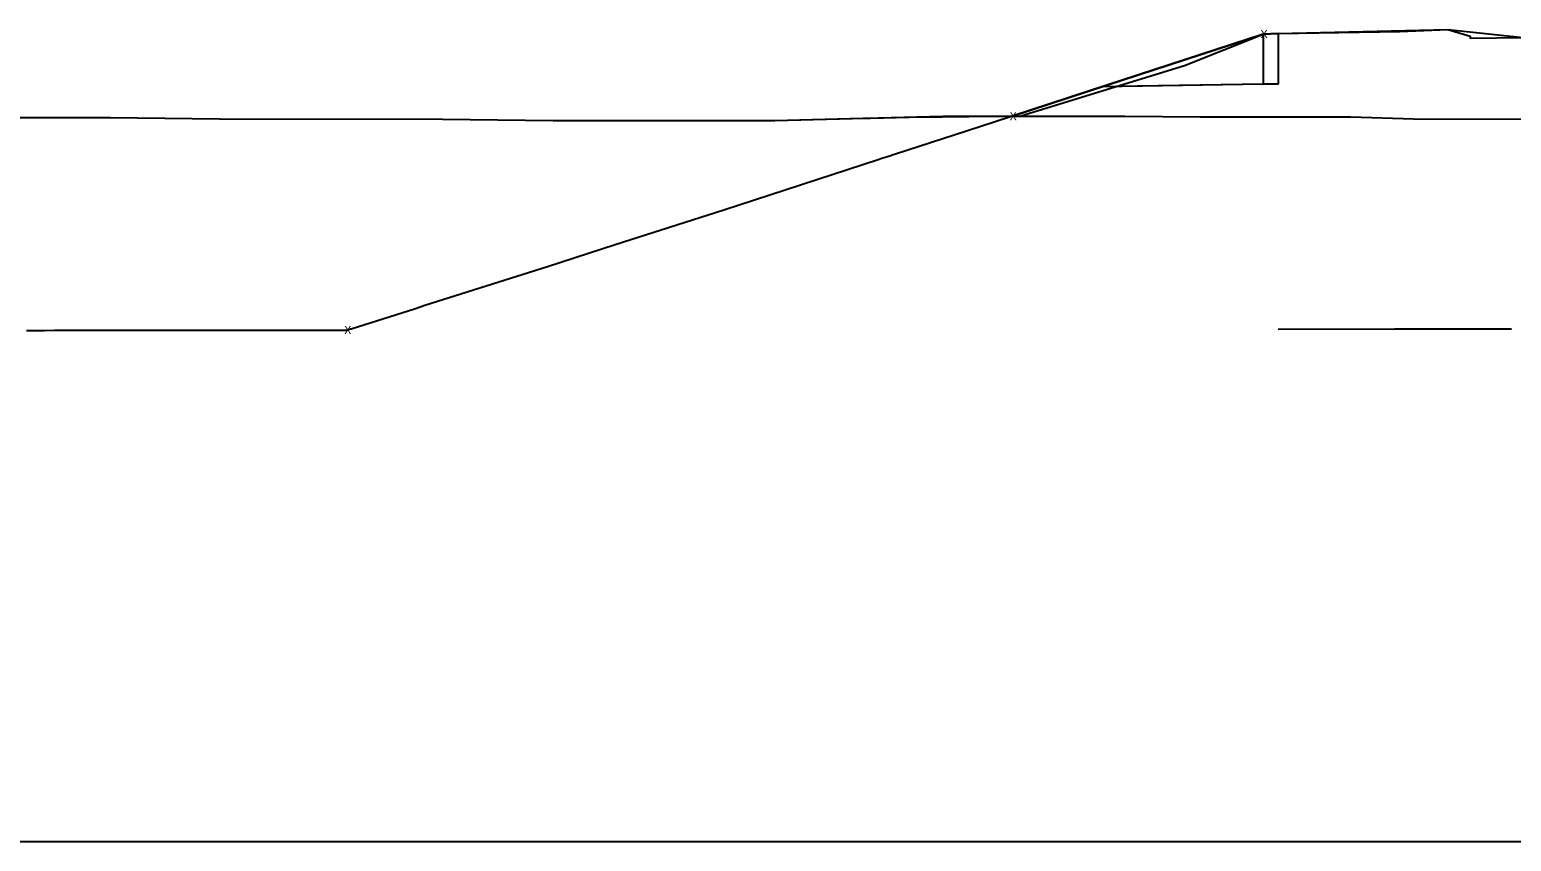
# Model space of a CAD drawing. Extents: x -26 to 303, y -16 to 6048.
# Drawn here: x 85.28 to 129.73, y 4500 to 4524.35 of the extents above; entities that cross this region are included whole.
import ezdxf

# ---------------------------------------------------------------- set-up
doc = ezdxf.new("R2010")
doc.units = 0
for name, color, linetype in [('CONST_DCH', 7, 'Continuous'), ('CONST_LV3', 7, 'Continuous'), ('DTM_P_FINISHED_GRADE2', 7, 'Continuous'), ('DTM_TEMP_DROP', 7, 'Continuous'), ('DTM_X_GROUND', 7, 'Continuous'), ('X_PROFILES_1', 7, 'Continuous'), ('XS_CELL', 7, 'Continuous'), ('XS_M_SHAPES_EARTHWORK', 7, 'Continuous'), ('XS_P_GROUND', 7, 'Continuous'), ('XS_P_SHOULDER', 7, 'Continuous'), ('XS_P_SUBGRADE_GRANULAR', 7, 'Continuous'), ('XS_P_SUBGRADE_GRANULAR_B', 7, 'Continuous')]:
    doc.layers.add(name, color=color, linetype=linetype)

msp = doc.modelspace()

# ---------------------------------------------------------------- linework, layer by layer
at = {"layer": 'CONST_LV3'}
for points in [[(94.797, 4515.34), (94.908, 4515.375), (94.923, 4515.379), (96.854, 4515.99), (97.139, 4516.081), (100.815, 4517.247), (102.845, 4517.902), (106.108, 4518.949), (110.735, 4520.455), (110.846, 4520.491), (111.118, 4520.58), (111.155, 4520.592), (111.252, 4520.623), (113.386, 4521.311), (122.281, 4524.218), (122.395, 4524.222), (122.734, 4524.235)], [(122.734, 4524.235), (122.282, 4524.218), (117.591, 4522.68), (114.756, 4521.754)], [(122.281, 4524.218), (122.734, 4524.235)]]:
    msp.add_lwpolyline(points, dxfattribs=at)
at = {"layer": 'DTM_P_FINISHED_GRADE2'}
msp.add_lwpolyline([(114.756, 4521.754), (114.983, 4521.754), (119.921, 4523.272), (122.282, 4524.218), (122.734, 4524.235), (126.381, 4524.293), (127.822, 4524.351), (128.49, 4524.156), (128.492, 4524.09), (130.083, 4524.118)], dxfattribs=at)
at = {"layer": 'DTM_X_GROUND'}
for points in [[(80.968, 4521.716), (87.694, 4521.711), (90.976, 4521.673), (97.666, 4521.666), (100.982, 4521.628), (107.639, 4521.62), (110.27, 4521.691), (110.506, 4521.697), (111.662, 4521.728), (112.674, 4521.738), (114.259, 4521.754), (114.756, 4521.754), (114.927, 4521.754), (114.983, 4521.754), (119.921, 4523.272), (122.282, 4524.218), (122.394, 4524.222), (122.734, 4524.235), (127.822, 4524.351), (130.083, 4524.118)], [(39.4, 4521.777), (41.51, 4521.773), (49.291, 4521.763), (51.672, 4521.759), (59.183, 4521.749), (61.569, 4521.803), (68.443, 4521.799), (71.992, 4521.729), (78.481, 4521.721), (80.968, 4521.716), (87.694, 4521.711), (90.976, 4521.673), (97.666, 4521.666), (100.982, 4521.628), (107.639, 4521.62), (112.674, 4521.755), (118.136, 4521.753), (120.403, 4521.738), (124.916, 4521.736), (126.788, 4521.673), (132.667, 4521.665)]]:
    msp.add_lwpolyline(points, dxfattribs=at)
at = {"layer": 'XS_CELL'}
msp.add_line((0, 4500), (150, 4500), dxfattribs=at)
at = {"layer": 'XS_M_SHAPES_EARTHWORK'}
for points in [[(117.869, 4522.641), (119.921, 4523.272), (122.282, 4524.218), (122.394, 4524.222), (122.734, 4524.235), (122.734, 4522.721), (122.283, 4522.714)], [(114.756, 4521.754), (114.927, 4521.754), (114.983, 4521.754), (117.869, 4522.641), (117.45, 4522.634)]]:
    msp.add_lwpolyline(points, close=True, dxfattribs=at)
at = {"layer": 'XS_P_GROUND'}
for points in [[(94.797, 4515.34), (94.908, 4515.375), (94.923, 4515.379), (96.854, 4515.99), (97.139, 4516.081), (100.815, 4517.247), (102.845, 4517.902), (106.108, 4518.949), (110.735, 4520.455), (110.846, 4520.491), (111.118, 4520.58), (111.155, 4520.592), (111.252, 4520.623), (113.386, 4521.311), (122.281, 4524.218)], [(114.756, 4521.754), (117.591, 4522.68), (122.282, 4524.218)], [(85.19, 4515.33), (85.725, 4515.33), (86.031, 4515.331), (86.425, 4515.331), (90.789, 4515.336), (90.879, 4515.336), (90.949, 4515.336), (91.036, 4515.336), (91.04, 4515.336), (91.476, 4515.336), (91.478, 4515.336), (91.646, 4515.337), (91.739, 4515.337), (91.933, 4515.337), (93.442, 4515.339), (93.505, 4515.339), (94.772, 4515.34)], [(94.772, 4515.34), (94.797, 4515.34)], [(122.734, 4515.37), (126.225, 4515.374), (126.821, 4515.375), (127.743, 4515.376), (128.783, 4515.377), (129.625, 4515.379), (129.728, 4515.379)]]:
    msp.add_lwpolyline(points, dxfattribs=at)
at = {"layer": 'XS_P_SHOULDER'}
msp.add_lwpolyline([(122.282, 4524.218), (122.734, 4524.235)], dxfattribs=at)
at = {"layer": 'XS_P_SUBGRADE_GRANULAR_B'}
for points in [[(122.282, 4524.218), (122.282, 4524.17), (122.283, 4522.714)], [(122.283, 4522.714), (117.446, 4522.634)], [(122.283, 4522.714), (122.734, 4522.721)]]:
    msp.add_lwpolyline(points, dxfattribs=at)

# ---------------------------------------------------------------- texts
at = {"layer": 'CONST_DCH'}
msp.add_text('X', height=0.24, dxfattribs=at).set_placement((94.718, 4515.22))
at = {"layer": 'DTM_TEMP_DROP'}
for p in [(114.677, 4521.634), (94.718, 4515.22)]:
    msp.add_text('X', height=0.24, dxfattribs=at).set_placement(p)
at = {"layer": 'X_PROFILES_1'}
msp.add_text('X', height=0.24, dxfattribs=at).set_placement((122.202, 4524.098))
at = {"layer": 'XS_P_GROUND'}
msp.add_text('X', height=0.24, dxfattribs=at).set_placement((122.203, 4524.098))
at = {"layer": 'XS_P_SUBGRADE_GRANULAR'}
msp.add_text('X', height=0.24, dxfattribs=at).set_placement((114.677, 4521.634))

doc.saveas('drawing.dxf')
